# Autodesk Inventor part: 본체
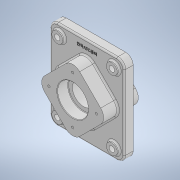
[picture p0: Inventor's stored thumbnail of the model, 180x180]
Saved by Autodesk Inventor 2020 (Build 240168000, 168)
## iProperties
Created: 2021-07
Part Number: 본체
Material: 일반
Document SubType Name: Modeling
Designer: Owner
Density: 1 g/cm^3
Appearance: 기본값
Mass: 807.977 g
Surface Area: 961.758 cm^2
Volume: 807.977 cm^3
Author: Owner
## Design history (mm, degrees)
sketch "스케치1"
  geometry: L1 (75, -90)-(-75, -90); L2 (-75, -90)-(-75, 90); L3 (-75, 90)-(75, 90); L4 (75, 90)-(75, -90); L5 (75, -90)-(-75, 90); L6 (-75, -90)-(75, 90); 1 further point
  constraints: 12 end point, 2 midpoint, 2 parallel, 1 horizontal, 1 perpendicular
  dimensions: "d0" = 150 distance of L2.end L3.end; "d1" = 180 distance of L1.end L2.end
extrude "돌출1" new body sketch "스케치1" stored distance "d2" = 18; taper "d3" = 0 deg
sketch "스케치2"
  geometry: L1 (70.711, 0)-(0, 70.711); L2 (0, 70.711)-(-70.711, 0); L3 (-70.711, 0)-(0, -70.711); L4 (0, -70.711)-(70.711, 0); L5 (70.711, 0)-(-70.711, 0); L6 (0, 70.711)-(0, -70.711); L7 (0, 0)-(0, -48.35)
  constraints: 14 end point, 2 midpoint, 2 parallel, 1 perpendicular, 1 vertical
  dimensions: "d4" = 100 distance between parallel lines of L4 L2; "d5" = 100 distance between parallel lines of L3 L1; "d6" = 45 deg angle of L3 L7
extrude "돌출2" join sketch "스케치2" distance "d7" = 29; taper "d8" = 0 deg
extrude "돌출3" join sketch "스케치2" distance "d9" = 41; taper "d10" = 0 deg
fillet "모깎기1" dims "d11" = 20
sketch "스케치3"
  geometry: 2 further points
  constraints: 1 coincident
hole "구멍1" sketch "스케치3" at (0, 0) diameter "d12" = 45; stored, may be unused: countersink angle "d16" = 90 deg, drill point angle "d18" = 118 deg; dims "d13" = 8, "d14" = 4, "d15" = 2, "d17" = 11
sketch "스케치4"
  geometry: C1 r 22.5 at (0, 0) reference; 2 further points
  constraints: 1 coincident
hole "구멍2" sketch "스케치4" at (0, 0) diameter "d19" = 62; stored, may be unused: countersink angle "d23" = 90 deg, drill point angle "d25" = 0 deg; dims "d20" = 8, "d21" = 4, "d22" = 2, "d24" = 22
sketch "스케치5"
  geometry: C1 r 22.5 at (0, 0) reference; 2 further points
  constraints: 1 coincident
hole "구멍3" sketch "스케치5" at (0, 0) diameter "d26" = 62; stored, may be unused: countersink angle "d30" = 90 deg, drill point angle "d32" = 0 deg; dims "d27" = 8, "d28" = 4, "d29" = 2, "d31" = 22
sketch "스케치6" dims "d33" = 96
  geometry: 3 further points
  constraints: 2 vertical alignment, 1 coincident, 2 other
hole "구멍4" sketch "스케치6" at (0, 48) diameter "d34" = 4.917; stored, may be unused: countersink angle "d38" = 90 deg, drill point angle "d40" = 118 deg; dims "d35" = 10, "d36" = 4, "d37" = 2, "d39" = 13
sketch "스케치7"
  geometry: C1 r 2.458 at (0, 48) reference; C2 r 2.458 at (0, 48) reference; 2 further points
  constraints: 1 coincident
hole "구멍5" sketch "스케치7" at (0, 48) diameter "d44" = 4.917; stored, may be unused: countersink angle "d48" = 90 deg, drill point angle "d50" = 118 deg; dims "d45" = 10, "d46" = 4, "d47" = 2, "d49" = 13
fillet "모깎기2" dims "d54" = 15
sketch "스케치8"
  geometry: L1 (-75, 75)-(-75, -75) reference; L2 (-55, 70)-(55, 70); L3 (-55, -70)-(55, -70); C1 r 11 at (-55, 70); C2 r 11 at (55, 70); C3 r 11 at (-55, -70); C4 r 11 at (55, -70); 3 further points
  constraints: 4 centre point, 4 end point, 2 horizontal, 2 midpoint, 2 vertical alignment
  dimensions: "d55" = 110 distance of L2.start L2.end; "d56" = 22 diameter of C1; "d57" = 22 diameter of C2; "d59" = 70 distance from line of point (0, 0) L2; "d60" = 22 diameter of C3; "d61" = 22 diameter of C4; "d62" = 110 distance of L3.start L3.end; "d63" = 70 distance from line of point (0, 0) L3
extrude "돌출4" join sketch "스케치8" distance "d64" = 5; taper "d65" = 0 deg
sketch "스케치9"
  geometry: C1 r 11 at (0, 0) reference; 2 further points
  constraints: 1 coincident
hole "구멍6" sketch "스케치9" at (0, 0) diameter "d66" = 11; stored, may be unused: countersink angle "d70" = 90 deg, drill point angle "d72" = 0 deg; dims "d67" = 10, "d68" = 4, "d69" = 2, "d71" = 13
sketch "스케치10"
  geometry: L1 (60, 90)-(-60, 90) reference; 2 further points
  constraints: 1 vertical alignment, 1 other
  dimensions: "d79" = 15 distance from line of L1 point (0, 75)
feature "엠보싱1" sketch "스케치10" dims "d0" = 150, "d1" = 180, "d80" = 0.5, "d81" = 0
fillet "모깎기3" dims "d82" = 3
chamfer "모따기1" distance "d83" = 1; stored, may be unused: second distance "d84" = 2, angle "d85" = 45 deg
fillet "모깎기4" dims "d86" = 1
node "솔리드1"
pattern_circular "원형 패턴1" dims angle "d42" = 360 deg
pattern_circular "원형 패턴2" dims angle "d52" = 360 deg
pattern_linear "직사각형 패턴1" dims "d75" = 110, "d78" = 140
feature "A9D066F2-1C7D-4E18-AEED-F7BC21143FA4" dims "d12" = 45, "d13" = 8, "d14" = 4, "d15" = 2, "d16" = 90 deg, "d17" = 11, "d18" = 118 deg
